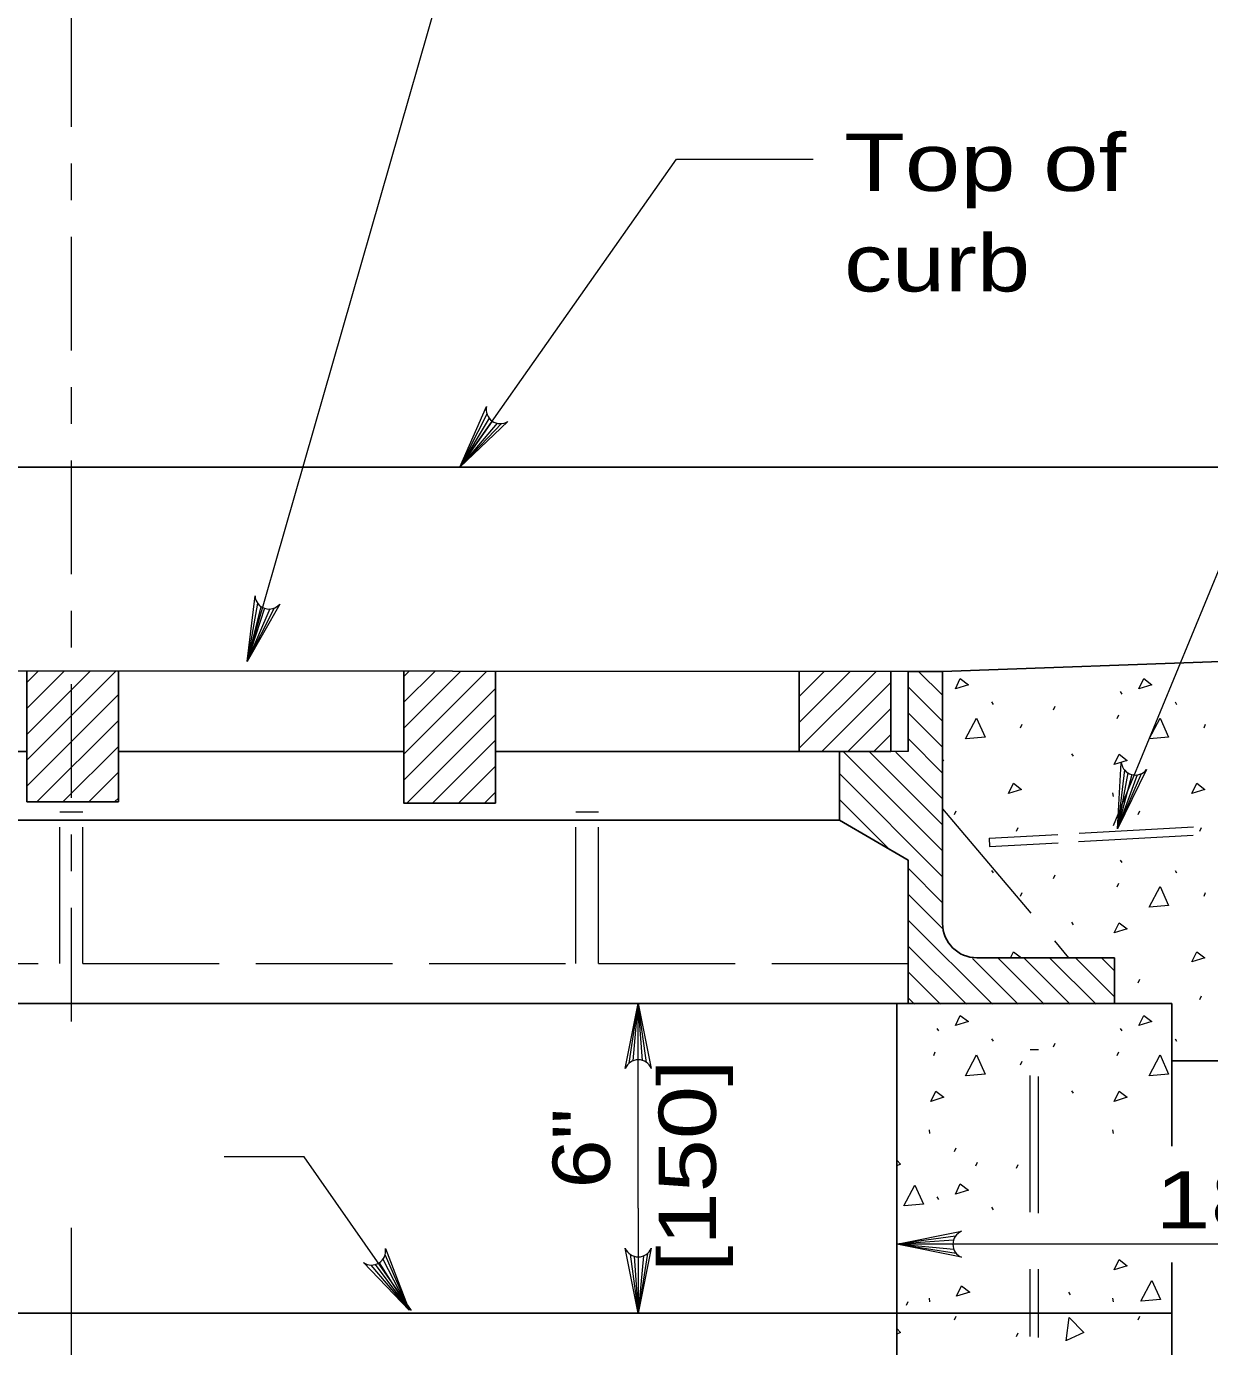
# Model space of a CAD drawing. Extents: x 1083.1 to 1117.1, y 719.4 to 763.4.
# Drawn here: x 1094.324 to 1097.549, y 732.95 to 736.55 of the extents above; entities that cross this region are included whole.
import ezdxf
from ezdxf.enums import TextEntityAlignment as Align

# ---------------------------------------------------------------- set-up
doc = ezdxf.new("R2010")
doc.units = 0
doc.header["$LTSCALE"] = 0.062
for name, pattern in [('DOT_DASHED', [7.7, 5, -1.2, 0.3, -1.2]), ('LONG_DASHED', [7.5, 6, -1.5]), ('MEDIUM_DASHED', [4.5, 3, -1.5])]:
    doc.linetypes.add(name, pattern=pattern)
doc.layers.add('1', color=7, linetype='Continuous', lineweight=13)

msp = doc.modelspace()

# ---------------------------------------------------------------- linework, layer by layer
at = {"layer": '1'}
for p, q in [((1094.92517, 734.81767), (1095.72283, 737.59625)), ((1097.287, 734.37075), (1098.44717, 737.18817)), ((1095.50533, 735.34842), (1096.09575, 736.1875)), ((1096.09575, 736.1875), (1096.46867, 736.1875)), ((1095.57917, 735.4925), (1095.50533, 735.34842)), ((1095.58517, 735.48167), (1095.50533, 735.34842)), ((1095.59342, 735.47375), (1095.50533, 735.34842)), ((1095.60683, 735.46783), (1095.50533, 735.34842)), ((1095.61892, 735.46683), (1095.50533, 735.34842)), ((1094.95408, 734.97692), (1094.92517, 734.81767)), ((1094.96292, 734.96825), (1094.92517, 734.81767)), ((1094.9995, 734.96392), (1094.92517, 734.81767)), ((1094.97317, 734.96317), (1094.92517, 734.81767)), ((1094.98775, 734.96133), (1094.92517, 734.81767)), ((1097.52275, 734.81483), (1097.52342, 734.81625)), ((1094.3245, 734.61942), (1094.49717, 734.79217)), ((1094.3245, 734.69017), (1094.4265, 734.79217)), ((1094.3245, 734.76083), (1094.35583, 734.79217)), ((1094.3245, 734.54875), (1094.56775, 734.79208)), ((1095.35242, 734.77758), (1095.36608, 734.79125)), ((1095.35242, 734.70683), (1095.43683, 734.79125)), ((1095.35242, 734.63617), (1095.5075, 734.79125)), ((1095.35242, 734.56542), (1095.57825, 734.79125)), ((1096.4305, 734.72292), (1096.49883, 734.79125)), ((1096.4305, 734.65217), (1096.56958, 734.79125)), ((1096.4305, 734.58142), (1096.64033, 734.79125)), ((1096.82108, 734.72617), (1096.756, 734.79125)), ((1095.35242, 734.49475), (1095.60242, 734.74467)), ((1096.49225, 734.5725), (1096.6805, 734.76075)), ((1096.82108, 734.65542), (1096.72733, 734.74917)), ((1094.3245, 734.47808), (1094.57442, 734.728)), ((1096.95492, 734.70783), (1096.95933, 734.70117)), ((1097.30533, 734.73608), (1097.30983, 734.72942)), ((1097.45492, 734.70783), (1097.45933, 734.70117)), ((1095.36033, 734.432), (1095.60242, 734.674)), ((1096.563, 734.5725), (1096.6805, 734.69)), ((1096.82108, 734.58475), (1096.72733, 734.6785)), ((1097.12383, 734.68608), (1097.12825, 734.69608)), ((1097.297, 734.66292), (1097.30142, 734.67292)), ((1094.35217, 734.43508), (1094.57442, 734.65733)), ((1097.03392, 734.63742), (1097.03833, 734.64742)), ((1097.53392, 734.63742), (1097.53833, 734.64742)), ((1095.43108, 734.432), (1095.60242, 734.60325)), ((1096.63367, 734.5725), (1096.6805, 734.61933)), ((1096.82108, 734.51408), (1096.72733, 734.60775)), ((1094.42292, 734.43508), (1094.57442, 734.58658)), ((1096.72733, 734.5725), (1096.53983, 734.5725)), ((1096.82108, 734.30192), (1096.55225, 734.57067)), ((1096.82108, 734.37267), (1096.623, 734.57067)), ((1096.82108, 734.44333), (1096.69367, 734.57067)), ((1097.17267, 734.56633), (1097.17708, 734.55967)), ((1095.50175, 734.432), (1095.60242, 734.53267)), ((1094.4935, 734.43508), (1094.57442, 734.516)), ((1096.82108, 734.23125), (1096.53983, 734.5125)), ((1097.31675, 734.52233), (1097.29783, 734.36158)), ((1097.32617, 734.51425), (1097.29783, 734.36158)), ((1097.36292, 734.51217), (1097.29783, 734.36158)), ((1097.33667, 734.50975), (1097.29783, 734.36158)), ((1097.35133, 734.50883), (1097.29783, 734.36158)), ((1095.5725, 734.432), (1095.60242, 734.46192)), ((1097.28483, 734.46), (1097.286, 734.45)), ((1094.56425, 734.43508), (1094.57442, 734.44525)), ((1096.67833, 734.30333), (1096.53983, 734.44175)), ((1096.85408, 734.40108), (1096.8585, 734.41108)), ((1097.35408, 734.40108), (1097.3585, 734.41108)), ((1097.02275, 734.3555), (1097.02725, 734.3655)), ((1097.52275, 734.3555), (1097.52725, 734.3655)), ((1097.30533, 734.27675), (1097.30983, 734.27008)), ((1096.82108, 734.1605), (1096.72733, 734.25425)), ((1096.95492, 734.2485), (1096.95933, 734.24183)), ((1097.12383, 734.22675), (1097.12825, 734.23675)), ((1097.45492, 734.2485), (1097.45933, 734.24183)), ((1097.297, 734.20358), (1097.30142, 734.21358)), ((1096.82108, 734.08983), (1096.72733, 734.18358)), ((1097.03392, 734.17808), (1097.03833, 734.18808)), ((1097.53392, 734.17808), (1097.53833, 734.18808)), ((1096.95692, 733.88333), (1096.72733, 734.11283)), ((1097.17267, 734.107), (1097.17708, 734.10033)), ((1096.88625, 733.88333), (1096.72733, 734.04217)), ((1097.02767, 733.88333), (1096.90267, 734.00825)), ((1097.09833, 733.88333), (1096.97333, 734.00825)), ((1097.16908, 733.88333), (1097.04408, 734.00825)), ((1097.23975, 733.88333), (1097.11475, 734.00825)), ((1097.28983, 733.904), (1097.1855, 734.00825)), ((1097.28983, 733.97467), (1097.25617, 734.00825)), ((1096.8155, 733.88333), (1096.72733, 733.9715)), ((1097.35408, 733.94175), (1097.3585, 733.95175)), ((1095.96692, 733.72292), (1095.99175, 733.88517)), ((1095.97733, 733.72908), (1095.99175, 733.88517)), ((1095.99175, 733.32792), (1095.99175, 733.88517)), ((1095.99175, 733.73192), (1095.99175, 733.88517)), ((1096.00308, 733.73025), (1095.99175, 733.88517)), ((1096.01417, 733.72483), (1095.99175, 733.88517)), ((1096.74483, 733.88333), (1096.72733, 733.90083)), ((1097.15783, 733.88475), (1097.15792, 733.88517)), ((1097.159, 733.88517), (1097.15883, 733.88508)), ((1097.52275, 733.89617), (1097.52725, 733.90617)), ((1096.80533, 733.81742), (1096.80983, 733.81075)), ((1097.30533, 733.81742), (1097.30983, 733.81075)), ((1096.95492, 733.78917), (1096.95933, 733.7825)), ((1097.12383, 733.76742), (1097.12825, 733.77742)), ((1097.45492, 733.78917), (1097.45933, 733.7825)), ((1096.797, 733.74425), (1096.80142, 733.75425)), ((1097.297, 733.74425), (1097.30142, 733.75425)), ((1097.03392, 733.71875), (1097.03833, 733.72875)), ((1097.17267, 733.64767), (1097.17708, 733.64108)), ((1096.78483, 733.54125), (1096.786, 733.53125)), ((1097.28483, 733.54125), (1097.286, 733.53125)), ((1096.85408, 733.48233), (1096.8585, 733.49233)), ((1095.08058, 733.46717), (1094.863, 733.46717)), ((1095.37392, 733.04825), (1095.08058, 733.46717)), ((1096.91183, 733.443), (1096.91625, 733.453)), ((1097.02275, 733.43675), (1097.02725, 733.44675)), ((1096.80533, 733.35808), (1096.80983, 733.35142)), ((1095.99175, 733.32792), (1095.99175, 733.04142)), ((1096.95492, 733.32983), (1096.95933, 733.32317)), ((1094.44633, 733.0415), (1094.44633, 733.27425)), ((1096.85642, 733.25142), (1096.69608, 733.229)), ((1096.851, 733.24033), (1096.69608, 733.229)), ((1098.2145, 733.229), (1096.69608, 733.229)), ((1096.84933, 733.229), (1096.69608, 733.229)), ((1096.85217, 733.21458), (1096.69608, 733.229)), ((1096.85833, 733.20417), (1096.69608, 733.229)), ((1095.30125, 733.19925), (1095.36717, 733.049)), ((1095.96925, 733.20183), (1095.99175, 733.0415)), ((1095.98042, 733.19642), (1095.99175, 733.0415)), ((1096.0165, 733.20375), (1095.99175, 733.0415)), ((1096.00608, 733.19758), (1095.99175, 733.0415)), ((1095.99175, 733.19475), (1095.99175, 733.0415)), ((1095.26242, 733.17233), (1095.36717, 733.049)), ((1095.27467, 733.17375), (1095.36717, 733.049)), ((1095.28508, 733.17842), (1095.36717, 733.049)), ((1095.29575, 733.1885), (1095.36717, 733.049)), ((1097.16483, 733.09808), (1097.16925, 733.0915)), ((1096.72267, 733.06267), (1096.72708, 733.07267)), ((1096.78483, 733.08192), (1096.786, 733.07192)), ((1097.28483, 733.08192), (1097.286, 733.07192)), ((1096.85408, 733.023), (1096.8585, 733.033)), ((1097.35408, 733.023), (1097.3585, 733.033)), ((1097.02275, 732.9775), (1097.02725, 732.9875))]:
    msp.add_line(p, q, dxfattribs=at)
at = {"layer": '1', "linetype": 'DOT_DASHED'}
for p, q in [((1094.44633, 733.83625), (1094.44633, 737.05917)), ((1094.44633, 731.04717), (1094.44633, 733.19283))]:
    msp.add_line(p, q, dxfattribs=at)
at = {"layer": '1', "lineweight": 25}
for p, q in [((1096.82108, 734.79125), (1097.7735, 734.82517)), ((1096.72733, 734.79125), (1092.13392, 734.79308)), ((1094.3245, 734.79225), (1094.3245, 734.43508)), ((1094.57442, 734.43508), (1094.57442, 734.79208)), ((1095.60242, 734.79125), (1095.60242, 734.432)), ((1096.6805, 734.79125), (1096.6805, 734.5725)), ((1096.82108, 734.10383), (1096.82108, 734.79125)), ((1094.3245, 734.5725), (1093.54017, 734.5725)), ((1095.35242, 734.5725), (1094.57442, 734.5725)), ((1096.4305, 734.5725), (1095.60242, 734.5725)), ((1094.3245, 734.43508), (1094.57442, 734.43508)), ((1092.32142, 734.38508), (1096.53983, 734.38508)), ((1091.19642, 733.88517), (1097.44608, 733.88517)), ((1096.69608, 730.80725), (1096.69608, 733.88517)), ((1097.44608, 733.88517), (1097.44608, 733.49633))]:
    msp.add_line(p, q, dxfattribs=at)
at = {"layer": '1', "linetype": 'LONG_DASHED'}
for p, q in [((1096.82108, 734.41633), (1097.16483, 734.01008)), ((1094.41508, 733.99458), (1094.41508, 734.40858)), ((1094.41508, 734.40858), (1094.4775, 734.40858)), ((1094.4775, 733.99458), (1094.4775, 734.40858)), ((1095.82117, 733.99458), (1095.82117, 734.40858)), ((1095.82117, 734.40858), (1095.88367, 734.40858)), ((1095.88367, 733.99458), (1095.88367, 734.40858)), ((1096.94792, 734.33633), (1097.13508, 734.34675)), ((1097.19208, 734.327), (1097.50408, 734.34433)), ((1097.1935, 734.34992), (1097.50558, 734.36725)), ((1096.94917, 734.31342), (1097.13633, 734.32383)), ((1093.04008, 733.99458), (1094.41508, 733.99458)), ((1094.4775, 733.99458), (1095.82117, 733.99458)), ((1095.88367, 733.99458), (1096.72733, 733.99458)), ((1097.05975, 733.31692), (1097.05975, 733.76017)), ((1097.05975, 733.76017), (1097.08258, 733.76017)), ((1097.08258, 733.31417), (1097.08258, 733.76017)), ((1097.05975, 733.0415), (1097.05975, 733.16117)), ((1097.08258, 733.0415), (1097.08258, 733.16117)), ((1097.05975, 732.9775), (1097.05975, 733.0415)), ((1097.08258, 732.97475), (1097.08258, 733.0415))]:
    msp.add_line(p, q, dxfattribs=at)
at = {"layer": '1', "linetype": 'MEDIUM_DASHED'}
msp.add_line((1096.94792, 734.33633), (1096.94917, 734.31342), dxfattribs=at)
at = {"layer": '1'}
for points in [[(1095.63617, 735.47292), (1095.50533, 735.34842), (1095.57817, 735.51367)], [(1095.01425, 734.97475), (1094.92517, 734.81767), (1094.947, 734.99692)], [(1096.884, 734.60742), (1096.914, 734.664), (1096.93733, 734.61192), (1096.88517, 734.60742)], [(1097.384, 734.60742), (1097.414, 734.664), (1097.43733, 734.61192), (1097.38517, 734.60742)], [(1096.82108, 734.55133), (1096.82475, 734.54858), (1096.82108, 734.54742)], [(1097.377, 734.52383), (1097.29783, 734.36158), (1097.30842, 734.54183)], [(1097.384, 734.14808), (1097.414, 734.20467), (1097.43733, 734.15258), (1097.38517, 734.14808)], [(1097.00625, 734.01008), (1097.01417, 734.02658), (1097.03608, 734.01008)], [(1095.95633, 733.70808), (1095.99175, 733.88517), (1096.02717, 733.70808)], [(1096.884, 733.68875), (1096.914, 733.74542), (1096.93733, 733.69325), (1096.88517, 733.68875)], [(1097.384, 733.68875), (1097.414, 733.74542), (1097.43733, 733.69325), (1097.38517, 733.68875)], [(1096.69608, 733.45833), (1096.70642, 733.44767), (1096.69608, 733.44292)], [(1096.71558, 733.334), (1096.74558, 733.39067), (1096.76892, 733.3385), (1096.71675, 733.334)], [(1096.87317, 733.19358), (1096.69608, 733.229), (1096.87317, 733.26442)], [(1095.30225, 733.2175), (1095.36717, 733.049), (1095.24242, 733.17958)], [(1096.02717, 733.21858), (1095.99175, 733.0415), (1095.95633, 733.21858)], [(1097.36183, 733.07392), (1097.39183, 733.13058), (1097.41517, 733.07842), (1097.363, 733.07392)], [(1097.15783, 732.966), (1097.16667, 733.02942), (1097.20642, 732.98833), (1097.15883, 732.96633)], [(1096.69608, 732.999), (1096.70642, 732.98833), (1096.69608, 732.98358)]]:
    msp.add_lwpolyline(points, dxfattribs=at)
at = {"layer": '1', "lineweight": 25}
for points in [[(1090.0715, 735.34842), (1091.29683, 735.34842), (1093.0845, 735.34842), (1094.87617, 735.34842), (1097.69617, 735.34842)], [(1098.83133, 735.34842), (1098.83133, 733.72892), (1097.44608, 733.72892)], [(1095.35242, 734.79125), (1095.35242, 734.432), (1095.60242, 734.432)], [(1096.6805, 734.5725), (1096.4305, 734.5725), (1096.4305, 734.79133)], [(1096.82108, 734.79125), (1096.72733, 734.79125), (1096.72733, 734.5725)], [(1096.53983, 734.5725), (1096.53983, 734.38508), (1096.72733, 734.27683), (1096.72733, 733.88517)], [(1097.28983, 733.88517), (1097.28983, 734.01008), (1096.91483, 734.01008)], [(1097.44608, 733.17933), (1097.44608, 729.87108), (1097.44608, 727.90158)], [(1091.19642, 733.0415), (1092.27317, 733.0415), (1097.44608, 733.0415)]]:
    msp.add_lwpolyline(points, dxfattribs=at)
at = {"layer": '1'}
for points in [[(1096.85625, 734.74383), (1096.86958, 734.77158), (1096.89183, 734.75492)], [(1097.35625, 734.74383), (1097.36958, 734.77158), (1097.39183, 734.75492)], [(1097.28917, 734.5375), (1097.3025, 734.56525), (1097.32475, 734.54858)], [(1097.00083, 734.45825), (1097.01417, 734.486), (1097.03633, 734.46933)], [(1097.50083, 734.45825), (1097.51417, 734.486), (1097.53633, 734.46933)], [(1097.28917, 734.07817), (1097.3025, 734.10592), (1097.32475, 734.08925)], [(1097.50083, 733.99883), (1097.51417, 734.02658), (1097.53633, 734.00992)], [(1096.85625, 733.82517), (1096.86958, 733.85292), (1096.89183, 733.83625)], [(1097.35625, 733.82517), (1097.36958, 733.85292), (1097.39183, 733.83625)], [(1096.78917, 733.61883), (1096.8025, 733.64658), (1096.82475, 733.62992)], [(1097.28917, 733.61883), (1097.3025, 733.64658), (1097.32475, 733.62992)], [(1096.85625, 733.36583), (1096.86958, 733.39358), (1096.89183, 733.37692)], [(1097.28917, 733.1595), (1097.3025, 733.18725), (1097.32475, 733.17058)], [(1096.85958, 733.08767), (1096.87292, 733.11542), (1096.89517, 733.09875)]]:
    msp.add_lwpolyline(points, close=True, dxfattribs=at)
for centre, start, end in [((1095.61536, 735.50499), 166.97765, 302.80378), ((1094.98507, 734.9994), 183.83423, 319.66036), ((1097.34631, 734.54669), 187.40784, 323.23396), ((1095.99176, 733.69377), 22.08782, 157.91395), ((1096.88748, 733.22903), 112.08782, 247.91395), ((1095.26467, 733.2106), 234.45021, 10.27634), ((1095.99168, 733.2329), 202.08782, 337.91395)]:
    msp.add_arc(centre, 0.03822, start, end, dxfattribs=at)
at = {"layer": '1', "lineweight": 25}
msp.add_ellipse((1096.91484, 734.10386), major_axis=(-0.09375, 0), ratio=0.999895, start_param=6.2831853, end_param=7.8539816, dxfattribs=at)

# ---------------------------------------------------------------- texts
at = {"layer": '1'}
for s, width, p in [('Top of', 1.3, (1096.55275, 736.10108)), ('curb', 1.25, (1096.55275, 735.827))]:
    msp.add_text(s, height=0.156, dxfattribs=dict(at, width=width)).set_placement(p)
for s, width, p in [('[150]', 1.25, (1096.20317, 733.44308)), ('6"', 1.15, (1095.91417, 733.49067))]:
    msp.add_text(s, height=0.156, rotation=90, dxfattribs=dict(at, width=width)).set_placement(p, align=Align.CENTER)
at = {"layer": '1', "width": 1.3}
msp.add_text('18" [450]', height=0.156, dxfattribs=at).set_placement((1097.93929, 733.27225), align=Align.CENTER)

doc.saveas('drawing.dxf')
